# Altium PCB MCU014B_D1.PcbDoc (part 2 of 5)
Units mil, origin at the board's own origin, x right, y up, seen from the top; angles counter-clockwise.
Board outline 2300.04 x 4058 mil, 4 copper layers (TOP, GND, PWR, BOTTOM), stack 48.84 mil thick; 371 components, 238 nets, 1148 pads, 688 vias.
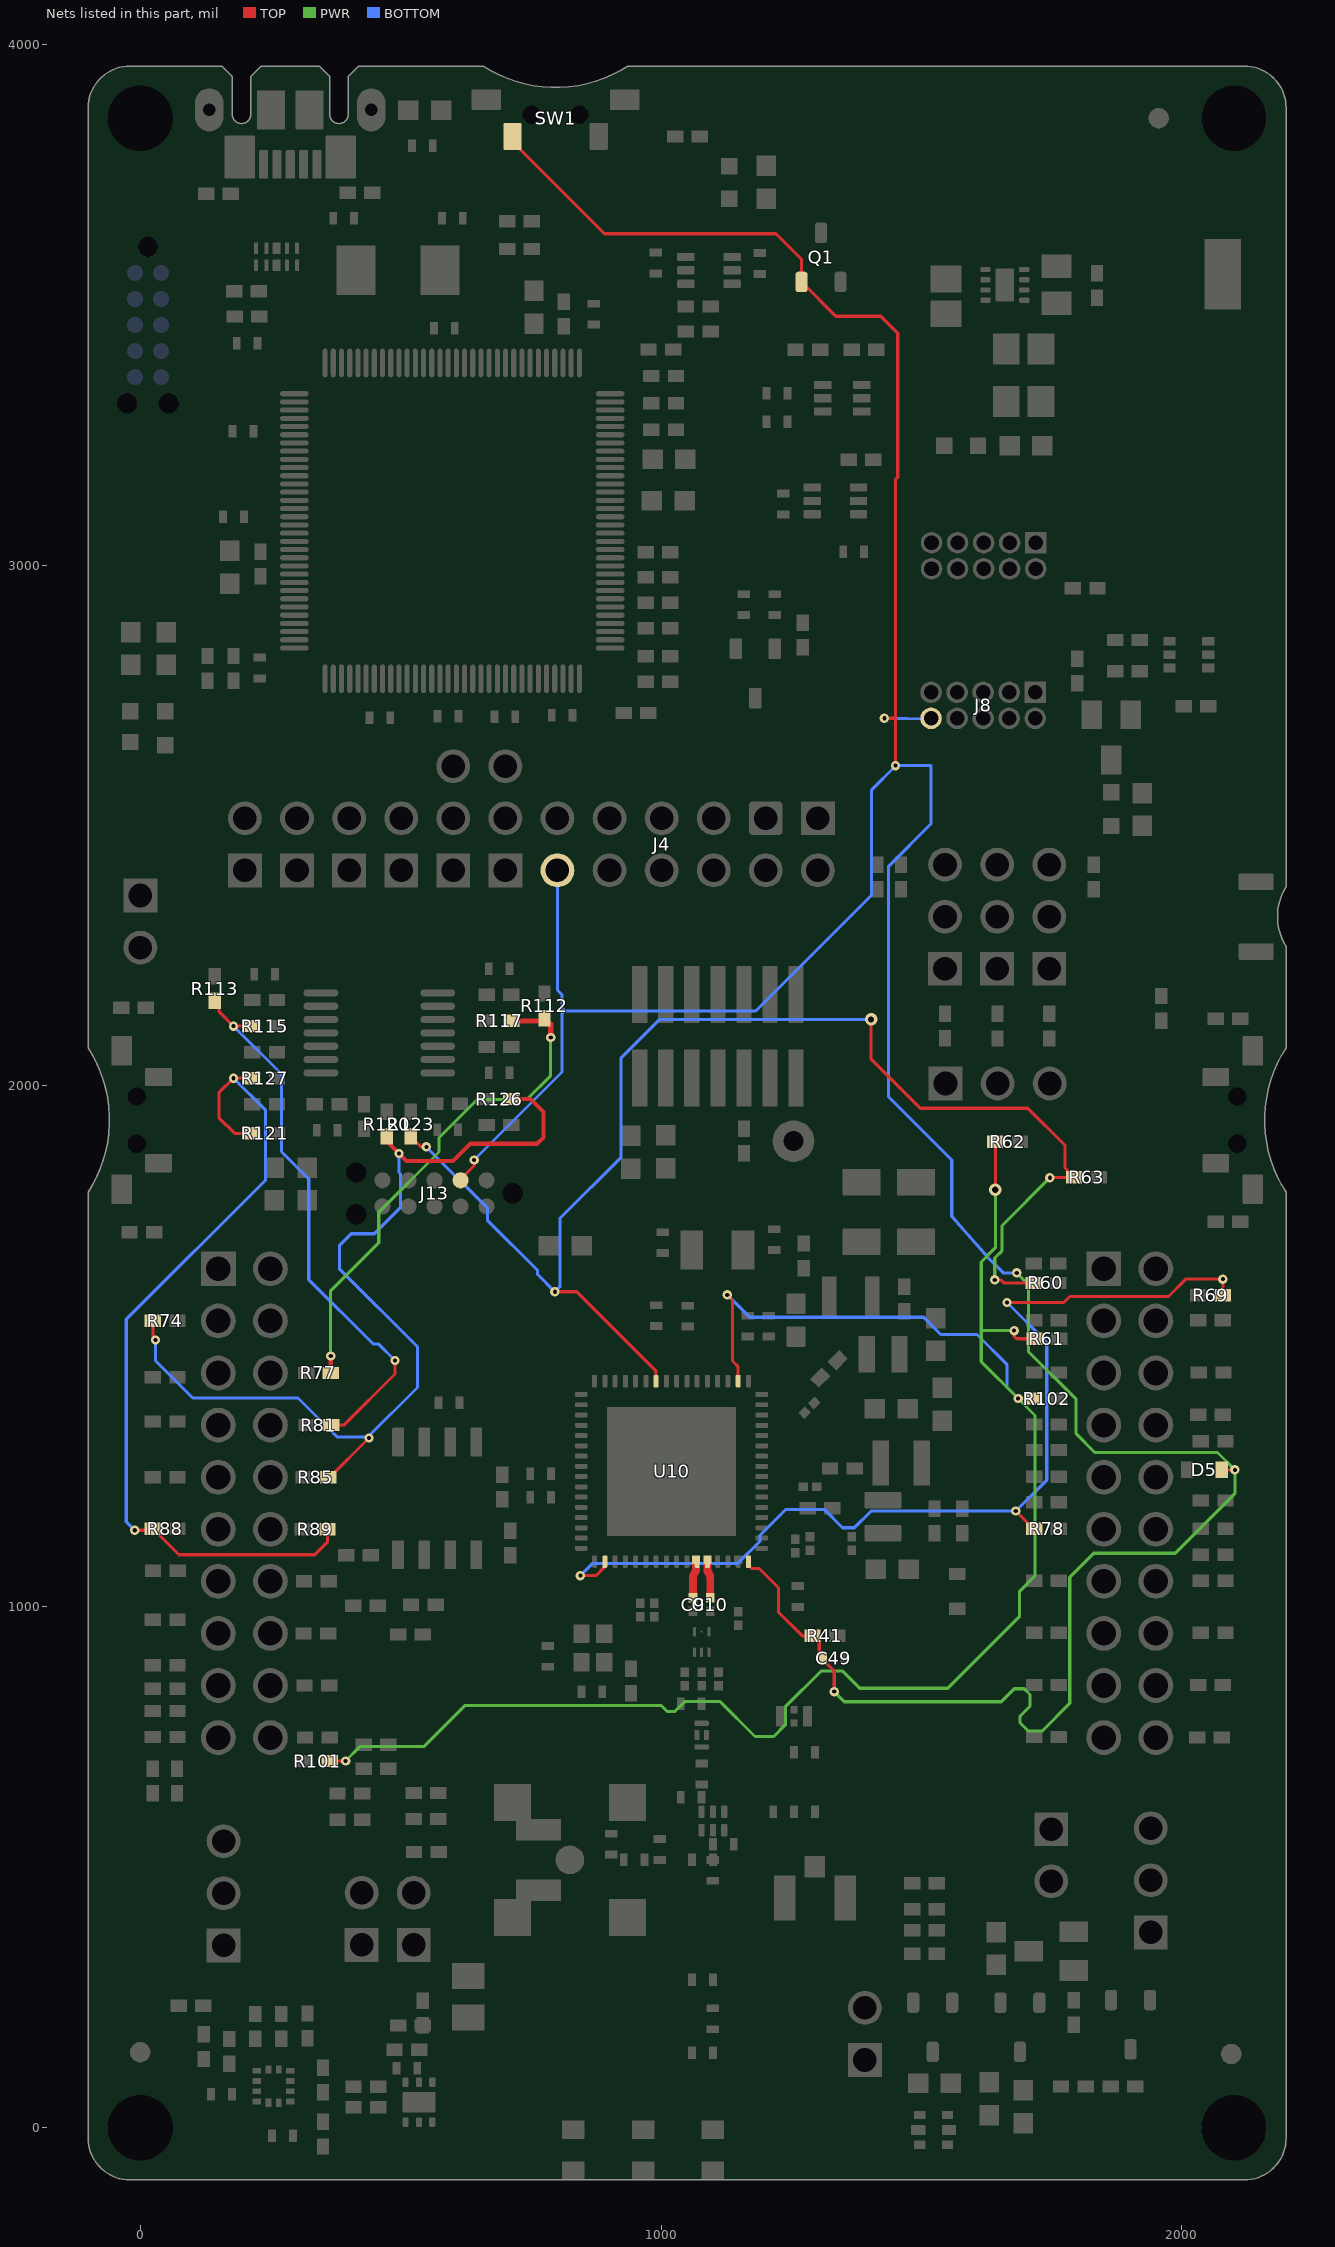
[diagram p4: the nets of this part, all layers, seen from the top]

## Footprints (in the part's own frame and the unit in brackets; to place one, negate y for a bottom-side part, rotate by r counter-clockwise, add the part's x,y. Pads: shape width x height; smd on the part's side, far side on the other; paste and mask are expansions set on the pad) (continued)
PDT0128A [mm] "Thin QFP, 128-Leads, Body 14x14mm, Pitch 0.4mm"
  oval 1.4x0.25 smd: 1(-7.7,6.2) 2(-7.7,5.8) 3(-7.7,5.4) 4(-7.7,5) 5(-7.7,4.6) 6(-7.7,4.2) 7(-7.7,3.8) 8(-7.7,3.4) 9(-7.7,3) 10(-7.7,2.6) 11(-7.7,2.2) 12(-7.7,1.8) 13(-7.7,1.4) 14(-7.7,1) 15(-7.7,0.6) 16(-7.7,0.2) 17(-7.7,-0.2) 18(-7.7,-0.6) 19(-7.7,-1) 20(-7.7,-1.4) 21(-7.7,-1.8) 22(-7.7,-2.2) 23(-7.7,-2.6) 24(-7.7,-3) 25(-7.7,-3.4) 26(-7.7,-3.8) 27(-7.7,-4.2) 28(-7.7,-4.6) 29(-7.7,-5) 30(-7.7,-5.4) 31(-7.7,-5.8) 32(-7.7,-6.2) 65(7.7,-6.2) 66(7.7,-5.8) 67(7.7,-5.4) 68(7.7,-5) 69(7.7,-4.6) 70(7.7,-4.2) 71(7.7,-3.8) 72(7.7,-3.4) 73(7.7,-3) 74(7.7,-2.6) 75(7.7,-2.2) 76(7.7,-1.8) 77(7.7,-1.4) 78(7.7,-1) 79(7.7,-0.6) 80(7.7,-0.2) 81(7.7,0.2) 82(7.7,0.6) 83(7.7,1) 84(7.7,1.4) 85(7.7,1.8) 86(7.7,2.2) 87(7.7,2.6) 88(7.7,3) 89(7.7,3.4) 90(7.7,3.8) 91(7.7,4.2) 92(7.7,4.6) 93(7.7,5) 94(7.7,5.4) 95(7.7,5.8) 96(7.7,6.2)
  oval 0.25x1.4 smd: 33(-6.2,-7.7) 34(-5.8,-7.7) 35(-5.4,-7.7) 36(-5,-7.7) 37(-4.6,-7.7) 38(-4.2,-7.7) 39(-3.8,-7.7) 40(-3.4,-7.7) 41(-3,-7.7) 42(-2.6,-7.7) 43(-2.2,-7.7) 44(-1.8,-7.7) 45(-1.4,-7.7) 46(-1,-7.7) 47(-0.6,-7.7) 48(-0.2,-7.7) 49(0.2,-7.7) 50(0.6,-7.7) 51(1,-7.7) 52(1.4,-7.7) 53(1.8,-7.7) 54(2.2,-7.7) 55(2.6,-7.7) 56(3,-7.7) 57(3.4,-7.7) 58(3.8,-7.7) 59(4.2,-7.7) 60(4.6,-7.7) 61(5,-7.7) 62(5.4,-7.7) 63(5.8,-7.7) 64(6.2,-7.7) 97(6.2,7.7) 98(5.8,7.7) 99(5.4,7.7) 100(5,7.7) 101(4.6,7.7) 102(4.2,7.7) 103(3.8,7.7) 104(3.4,7.7) 105(3,7.7) 106(2.6,7.7) 107(2.2,7.7) 108(1.8,7.7) 109(1.4,7.7) 110(1,7.7) 111(0.6,7.7) 112(0.2,7.7) 113(-0.2,7.7) 114(-0.6,7.7) 115(-1,7.7) 116(-1.4,7.7) 117(-1.8,7.7) 118(-2.2,7.7) 119(-2.6,7.7) 120(-3,7.7) 121(-3.4,7.7) 122(-3.8,7.7) 123(-4.2,7.7) 124(-4.6,7.7) 125(-5,7.7) 126(-5.4,7.7) 127(-5.8,7.7) 128(-6.2,7.7)
  silkscreen extent -7.7,-6.3 6.3,6.99, body extent -8,-8 8,8, height 1.07
PW0014A_N [mm] "TSOP, 14-Leads, Body 5x4.4mm, Pitch 0.65mm, IPC Medium Density"
  oval 1.7x0.35 smd: 1(-2.85,1.95) 2(-2.85,1.3) 3(-2.85,0.65) 4(-2.85,0) 5(-2.85,-0.65) 6(-2.85,-1.3) 7(-2.85,-1.95) 8(2.85,-1.95) 9(2.85,-1.3) 10(2.85,-0.65) 11(2.85,0) 12(2.85,0.65) 13(2.85,1.3) 14(2.85,1.95)
  silkscreen extent -1.85,-2.55 1.85,2.55, body extent -3.21,-2.5 3.21,2.5, height 1
RGK0064B [mm] "VQFN-64"
  rrect42% 0.6x0.24 smd: 1(-4.4,3.75) 2(-4.4,3.25) 3(-4.4,2.75) 4(-4.4,2.25) 5(-4.4,1.75) 6(-4.4,1.25) 7(-4.4,0.75) 8(-4.4,0.25) 9(-4.4,-0.25) 10(-4.4,-0.75) 11(-4.4,-1.25) 12(-4.4,-1.75) 13(-4.4,-2.25) 14(-4.4,-2.75) 15(-4.4,-3.25) 16(-4.4,-3.75) 33(4.4,-3.75) 34(4.4,-3.25) 35(4.4,-2.75) 36(4.4,-2.25) 37(4.4,-1.75) 38(4.4,-1.25) 39(4.4,-0.75) 40(4.4,-0.25) 41(4.4,0.25) 42(4.4,0.75) 43(4.4,1.25) 44(4.4,1.75) 45(4.4,2.25) 46(4.4,2.75) 47(4.4,3.25) 48(4.4,3.75)
  rrect42% 0.24x0.6 smd: 17(-3.75,-4.4) 18(-3.25,-4.4) 19(-2.75,-4.4) 20(-2.25,-4.4) 21(-1.75,-4.4) 22(-1.25,-4.4) 23(-0.75,-4.4) 24(-0.25,-4.4) 25(0.25,-4.4) 26(0.75,-4.4) 27(1.25,-4.4) 28(1.75,-4.4) 29(2.25,-4.4) 30(2.75,-4.4) 31(3.25,-4.4) 32(3.75,-4.4) 49(3.75,4.4) 50(3.25,4.4) 51(2.75,4.4) 52(2.25,4.4) 53(1.75,4.4) 54(1.25,4.4) 55(0.75,4.4) 56(0.25,4.4) 57(-0.25,4.4) 58(-0.75,4.4) 59(-1.25,4.4) 60(-1.75,4.4) 61(-2.25,4.4) 62(-2.75,4.4) 63(-3.25,4.4) 64(-3.75,4.4)
  rrect10% 1x1 on Top Paste: 65(-2.4,-2.4) 65(-2.4,-1.2) 65(-2.4,0) 65(-2.4,1.2) 65(-2.4,2.4) 65(-1.2,-2.4) 65(-1.2,-1.2) 65(-1.2,0) 65(-1.2,1.2) 65(-1.2,2.4) 65(0,-2.4) 65(0,-1.2) 65(0,0) 65(0,1.2) 65(0,2.4) 65(1.2,-2.4) 65(1.2,-1.2) 65(1.2,0) 65(1.2,1.2) 65(1.2,2.4) 65(2.4,-2.4) 65(2.4,-1.2) 65(2.4,0) 65(2.4,1.2) 65(2.4,2.4)
  rrect2% 6.3x6.3 smd paste-4: 65(0,0)
  silkscreen extent -4.7,-4.7 4.7,4.7, body extent -4.5,-4.5 4.5,4.5, height 1
Richwave_RTC6608OSP [mm] "SMD, 6-Leads, Body 1x1mm"
  rrect67% 0.45x0.15 smd: 1(-0.5,0.35) 3(-0.5,-0.35) 4(0.5,-0.35) 5(0.5,0) 6(0.5,0.35)
  rrect100% 0.1x0.1 smd: 2(-0.5,0)
  TOP region: -0.725,-0.076 -0.725,-0.076 -0.726,-0.076 -0.726,-0.075 -0.726,-0.075 -0.726,-0.075 -0.726,0.075 -0.726,0.075 -0.726,0.076 -0.725,0.076 -0.725,0.076 -0.725,0.076 -0.275,0.076 -0.101,0.225 -0.101,0.5 -0.101,0.5 -0.101,0.501 -0.1,0.501 -0.1,0.501 -0.1,0.501 0.1,0.501 0.1,0.501 0.101,0.501 0.101,0.5 0.101,0.5 0.101,0.5 0.101,0.226 0.15,0.226 0.15,0.226 0.151,0.226 0.151,0.225 0.151,0.225 0.151,0.225 0.151,-0.225 0.151,-0.225 0.151,-0.226 0.15,-0.226 0.15,-0.226 0.15,-0.226 0.101,-0.226 0.101,-0.5 0.101,-0.5 0.101,-0.501 0.1,-0.501 0.1,-0.501 0.1,-0.501 -0.1,-0.501 -0.1,-0.501 -0.101,-0.501 -0.101,-0.5 -0.101,-0.5 -0.101,-0.5 -0.101,-0.225 -0.275,-0.076
  silkscreen extent -1.05,0.45 -0.95,0.55, body extent -0.55,-0.55 0.55,0.55, height 0.41
Samtec_FTSH-105-01-x-D-K [mm] "Header, 1.27 mm, 5x2, TH"
  rect 1.05x1.05 hole 0.71: 1(-0.635,2.54)
  round 1.05 hole 0.71: 2(0.635,2.54) 3(-0.635,1.27) 4(0.635,1.27) 5(-0.635,0) 6(0.635,0) 7(-0.635,-1.27) 8(0.635,-1.27) 9(-0.635,-2.54) 10(0.635,-2.54)
  silkscreen extent -2.54,-3.17 2.54,3.2, body extent -2.54,-3.17 2.54,3.1, height 5.73
Samtec_FTSH-107-01-x-DV [mm] "Header, 1.27mm, 7x2, SMT"
  rect 2.79x0.74 smd: 1(-2.035,3.81) 2(2.035,3.81) 3(-2.035,2.54) 4(2.035,2.54) 5(-2.035,1.27) 6(2.035,1.27) 7(-2.035,0) 8(2.035,0) 9(-2.035,-1.27) 10(2.035,-1.27) 11(-2.035,-2.54) 12(2.035,-2.54) 13(-2.035,-3.81) 14(2.035,-3.81)
  silkscreen extent -2.32,4.68 -2.08,4.93, body extent -2.94,-4.48 2.9,4.41, height 5.97
SML-31_Red [mm] "Rohm"
  rect 0.8x0.8 smd: 1(-0.825,0) 2(0.825,0)
  silkscreen extent -1.93,-0.76 1.1,0.76, body extent -0.85,-0.45 0.85,0.45, height 0.91
SOD-523F [mm] "COMCHIP"
  rect 0.6x0.8 smd paste-0.05: 1(-0.85,0) 2(0.85,0)
  body extent -0.9,-0.5 0.9,0.5, height 0.85
SOP-8_150MIL [mm] "SOP, 8-Leads, Body 5.03x4mm, Pitch 1.27mm"
  rrect18% 1.4x0.57 smd: 1(-2.75,1.905) 2(-2.75,0.635) 3(-2.75,-0.635) 4(-2.75,-1.905) 5(2.75,-1.905) 6(2.75,-0.635) 7(2.75,0.635) 8(2.75,1.905)
  silkscreen extent -2,-2.5 2,2.5, body extent -2,-2.5 2,2.5, height 1.76
SOT-23 [mm] "SOT23, 3-Leads, Body 2.9x1.3mm, Pitch 0.95mm, Lead Span 2.5mm, IPC Medium Density"
  rrect50% 1x0.6 smd: 1(-1.2,0.95) 2(-1.2,-0.95) 3(1.2,0)
  silkscreen extent -1.62,-1.5 0.7,1.5, body extent -1.16,-1.45 1.21,1.45, height 1
SOT-363 [mm]
  rect 0.6x0.42 smd mask+0.051: 1(-0.95,0.65) 2(-0.95,0) 3(-0.95,-0.65) 4(0.95,-0.65) 5(0.95,0) 6(0.95,0.65)
  silkscreen extent -0.38,-1.02 0.38,1.02, body extent -1.1,-1.1 1.1,1.1, height 1.12
SSOT-3 [mm] "SuperSOT-3"
  rect 1x1.4 smd: 1(-0.95,-1.1) 2(0.95,-1.1) 3(0,1.1)
  silkscreen extent -1.53,-0.05 1.5,0.77, body extent -1.52,-0.76 1.52,0.76, height 1.12
SW_1188E [mm] "SMD, 4-Leads, Body 7.8x3.5mm"
  rrect10% 1x1.45 smd: 1(-1.1,3.375) 2(-1.1,-3.375)
  rrect11% 1.3x0.9 smd: 3(0.7,2.1) 4(0.7,-2.1)
  round 0 hole 0.9 unplated paste+0.127 mask+0.127: ""(-0.35,1.15) ""(-0.35,-1.15)
  silkscreen extent -1.97,-2.28 0.95,2.28, body extent -2.55,-3.9 1.05,3.9, height 3.5
SW_B3U-3000P [mm] "SMD, 2-Leads, Body 3x2.5mm"
  rrect12% 1.7x0.8 smd: 1(0,1.7) 2(0,-1.7)
  silkscreen extent 1.25,-1.5 1.25,1.5, body extent -1.95,-2 1.25,2, height 1.2
Tag_TC2050-NL#1 [mil] "Footprint for Tag-Connect TC2050 No-Legs cables"
  round 31 smd paste-15.75: 1(-25,100) 2(-25,50) 3(-25,0) 4(-25,-50) 5(-25,-100) 6(25,-100) 7(25,-50) 8(25,0) 9(25,50) 10(25,100)
  round 39 hole 39 unplated mask+5: MH1(0,150) MH2(-40,-150) MH3(40,-150)
  silkscreen extent -105,-200 75,200
Tag_TC2050-NL#2 [mil] "Footprint for Tag-Connect TC2050 No-Legs cables"
  round 31 smd paste-15.75: 1(-25,100) 2(-25,50) 3(-25,0) 4(-25,-50) 5(-25,-100) 6(25,-100) 7(25,-50) 8(25,0) 9(25,50) 10(25,100)
  round 31 hole 39 unplated paste+10 mask+5: MH1(0,150) MH2(-40,-150) MH3(40,-150)
  silkscreen extent -75,-200 75,200
TDK_DEA165538BT-2236B1-H [mm] "SMD, 3-Leads, Body 1.6x0.8mm"
  rrect40% 0.25x0.7 smd: 1(-0.575,0) 3(0.575,0)
  rrect41% 0.5x0.245 smd: 2(0,0.228) 2(0,-0.228)
  silkscreen extent -1,-0.65 1,0.65, body extent -0.87,-0.45 0.87,0.45, height 0.65
TDK_DEA202450BT-1294C1-H [mm] "SMD, 4-Leads, Body 2x1.25mm"
  rect 0.35x0.35 smd: 1(0,0.325) 3(0,-0.325)
  rect 0.45x1 smd: 2(0.65,0) 4(-0.65,0)
  silkscreen extent -1.17,-0.8 1.17,1, body extent -1.07,-0.67 1.07,0.67, height 0.8
TDK_DPX165950DT-8148A1 [mm] "SMD, 6-Leads, Body 1.6x0.8mm"
  rrect33% 0.6x0.3 smd mask+0: 1(-0.45,0.55) 2(-0.45,0) 3(-0.45,-0.55) 4(0.45,-0.55) 5(0.45,0) 6(0.45,0.55)
  silkscreen extent -0.4,-1 0.4,1.2, body extent -0.47,-0.88 0.48,0.87, height 0.7
TESTPOINT [mil]
  round 80 hole 37.99: 1(0,0)
Testpoint_Keystone_Miniature [mil] "Miniature SMT test point"
  rect 135x70 smd: 1(0,0)
  silkscreen extent -78,-46 78,45, body extent -52,-20 52,20, height 61
TI_Stacked_Overlay_Small [mil]
  silkscreen extent -418,-98 418,98
TI_Symbol_Overlay_Small [mil]
  silkscreen extent -90,-88 91,88
TXC_8Y [mm] "SMD, 4-Leads, Body 2x1.6mm"
  rect 0.8x0.9 smd: 1(-0.55,0.7) 2(-0.55,-0.7) 3(0.55,-0.7) 4(0.55,0.7)
  silkscreen extent -0.68,1.35 -0.42,1.6, body extent -0.85,-1.05 0.85,1.05, height 0.56
WEEE_Minimum [mil] "WEEElie bin"
  silkscreen extent -95,-172 99,104
WL-SMCW_YELLOW [mm] "WURTH"
  rect 0.8x0.8 smd: 1(-0.8,0) 2(0.8,0)
  silkscreen extent -1.9,-0.8 1.2,0.8, body extent -0.85,-0.45 0.85,0.45, height 0.8
Wurth_60900213421 [mil] "Shunt, 2.54mm, Black"
  round 1 on Mech3: 0(0,0)
  body extent -98,-48 98,48, height 236
WURTH_61300211121 [mm] "Header, 2.54mm, 2x1, TH"
  rect 1.65x1.65 hole 1.15: 1(-1.27,0)
  round 1.65 hole 1.15: 2(1.27,0)
  silkscreen extent -2.54,-1.27 2.54,1.6, body extent -2.54,-1.27 2.54,1.27, height 8.54
WURTH_61300311121 [mm] "Header, 2.54mm, 3x1, TH"
  rect 1.65x1.65 hole 1.15: 1(-2.54,0)
  round 1.65 hole 1.15: 2(0,0) 3(2.54,0)
  silkscreen extent -4.18,-1.27 3.81,1.27, body extent -3.81,-1.27 3.81,1.27, height 8.54
WURTH_61301021121 [mm] "Header, 2.54mm, 5x2, TH"
  rrect25% 1.65x1.65 hole 1.15: 1(-5.08,-1.27)
  round 1.65 hole 1.15: 2(-5.08,1.27) 3(-2.54,-1.27) 4(-2.54,1.27) 5(0,-1.27) 6(0,1.27) 7(2.54,-1.27) 8(2.54,1.27) 9(5.08,-1.27) 10(5.08,1.27)
  silkscreen extent -6.35,-2.9 6.35,2.54, body extent -6.35,-2.54 6.35,2.54, height 8.54
XTAL_ABM3 [mm] "Abracon recommended land pattern 12.28.10"
  rect 1.9x2.4 smd: 1(-2.05,0) 2(2.05,0)
  silkscreen extent -2.67,-1.78 2.67,1.78, body extent -2.6,-1.7 2.6,1.7, height 1.3
XTAL_ABS07 [mm] "ABRACON"
  rect 1.1x1.9 smd: 1(-1.25,0) 2(1.25,0)
  silkscreen extent -0.4,-1 0.4,1, body extent -1.65,-0.8 1.65,0.8, height 0.9

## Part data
C1: "CAP, CERM, 10 pF, 50 V, +/- 5%, C0G/NP0, 0402", Alternate Manufacturer=----, Alternate PartNumber=GRM1555C1H100JA01D, Cap_Case=0402, Manufacturer=MuRata, Supplier Part Number 1=81-GRM1555C1H100JA1D, TempCo=C0G/NP0, Tolerance_%=5%, Value1=Unknown, Value2=50V, ValueDisplayed=10pF
C2: library part CMP-0085845-1, "CAP, CERM, 8.2 pF, 50 V,+/- 3%, C0G/NP0, 0402", Alternate Manufacturer=MuRata, Alternate PartNumber=GRM1555C1H8R2CA01D, Cap_Case=0402, Manufacturer=Walsin, TempCo=C0G/NP0, Tolerance_%=3%, Value2=50V, ValueDisplayed=8.2pF
C3 C4 C5: library part CMP-0080073-1, "CAP, CERM, 0.5 pF, 50 V,+/- 20%, C0G/NP0, 0402", Cap_Case=0402, Manufacturer=MuRata, Supplier Part Number 1=490-8105-1-ND, TempCo=C0G/NP0, Tolerance_%=20%, Value2=50V, ValueDisplayed=0.5pF
C6: library part CMP-0080075-1, "CAP, CERM, 1.6 pF, 50 V,+/- 7%, C0G/NP0, 0201", Cap_Case=0201, Manufacturer=MuRata, Supplier Part Number 1=490-11312-1-ND, TempCo=C0G/NP0, Tolerance_%=7%, Value2=50V, ValueDisplayed=1.6pF
C7: library part CMP-0085853-1, "CAP, CERM, 1.9 pF, 50 V,+/- 2.6%, C0G/NP0, 0402", Alternate Manufacturer=MuRata, Alternate PartNumber=GRM1555C1H1R9WA01D, Cap_Case=0402, TempCo=C0G/NP0, Tolerance_%=2.6%, Value2=50V, ValueDisplayed=1.9pF
C8: library part CMP-0085854-1, "CAP, CERM, 2.2 pF, 50 V,+/- 4.5%, C0G/NP0, 0402", Alternate Manufacturer=MuRata, Alternate PartNumber=GRM1555C1H2R2BA01D, Cap_Case=0402, TempCo=C0G/NP0, Tolerance_%=4.5%, Value2=50V, ValueDisplayed=2.2pF
C9 C10: library part CMP-0080076-1, "CAP, CERM, 4.7 pF, 50 V,+/- 3%, C0G/NP0, 0201", Cap_Case=0201, Manufacturer=MuRata, Supplier Part Number 1=490-11332-1-ND, TempCo=C0G/NP0, Tolerance_%=3%, Value2=50V, ValueDisplayed=4.7pF
C11: "CAP, CERM, 1 pF, 50 V, +/- 10%, C0G/NP0, 0402", Alternate Manufacturer=----, Cap_Case=0402, Manufacturer=MuRata, PartNumber=GRM1555C1H1R0BA01D, Supplier Part Number 1=490-6206-1-ND, TempCo=C0G/NP0, Tolerance_%=10%, Value1=Unknown, Value2=50V, ValueDisplayed=1pF
C14 C15: library part CMP-0085847-1, "CAP, CERM, 100 pF, 25 V,+/- 5%, C0G/NP0, 0201", Alternate PartNumber=C0603C0G1E101J030BA, Cap_Case=0201, Manufacturer=Yageo, TempCo=C0G/NP0, Tolerance_%=5%, Value2=25V, ValueDisplayed=100pF
C17 C18 C19 C26 C28 C40 C41 C47 C48 C50 C52 C60 C61 C63 C75 C76 C77: library part CMP-0085850-1, "CAP, CERM, 0.1 µF, 16 V,+/- 10%, X7R, 0402", Alternate PartNumber=C1005X5R1A104K050BA, Cap_Case=0402, Manufacturer=Walsin, TempCo=X7R, Tolerance_%=10%, Value2=16V, ValueDisplayed=0.1µF
C20 C22 C24 C29 C30 C31 C35 C71 C72 C73 C74: library part CMP-0085842-1, "CAP, CERM, 0.01 µF, 50 V,+/- 10%, X7R, 0402", Alternate PartNumber=C1005X7R1C103K050BA, Cap_Case=0402, Manufacturer=Walsin, TempCo=X7R, Tolerance_%=10%, Value2=50V, ValueDisplayed=0.01µF
C21 C23: library part CMP-0085851-1, "CAP, CERM, 22 pF, 50 V,+/- 5%, C0G/NP0, 0402", Alternate PartNumber=GRM1555C1H220FA01D, Cap_Case=0402, Manufacturer=Walsin, TempCo=C0G/NP0, Tolerance_%=5%, Value2=50V, ValueDisplayed=22pF
C25 C27 C34 C36 C39: library part CMP-0085848-1, "CAP, CERM, 1 µF, 25 V,+/- 10%, X5R, 0402", Alternate PartNumber=C1005X5R1E105K050BC, Cap_Case=0402, Manufacturer="Samsung Electro-Mechanics", TempCo=X5R, Tolerance_%=10%, Value2=25V, ValueDisplayed=1µF
C32 C33 C38: "CAP, CERM, 0.1 uF, 25 V, +/- 10%, X5R, 0603", Alternate Manufacturer=Walsin, Alternate PartNumber=0603B104K250CT, Cap_Case=0603, Manufacturer=AVX, PartNumber=06033D104KAT2A, Supplier Part Number 1=478-1244-1-ND, TempCo=X5R, Tolerance_%=10%, Value1="0.048 ohm", Value2=25V, ValueDisplayed=0.1uF
C37: "CAP, CERM, 2.2 uF, 16 V, +/- 10%, X5R, 0402", Alternate Manufacturer=SAMSUNG, Alternate PartNumber=CL05A225KA5NUNC, Cap_Case=0402, Manufacturer=TDK, PartNumber=C1005X5R1C225K050BC, Supplier Part Number 1=445-9085-1-ND, TempCo=X5R, Tolerance_%=10%, Value1=Unknown, Value2=16V, ValueDisplayed=2.2uF
C42 C43 C45: "CAP, CERM, 4.7 uF, 6.3 V,+/- 20%, X6S, 0402", Alternate Manufacturer=SAMSUNG, Alternate PartNumber=CL05A475MQ5NRNC, Cap_Case=0402, Manufacturer="Taiyo Yuden", PartNumber=JMK105BC6475MV-F, Supplier Part Number 1=48Y4404, TempCo=X6S, Tolerance_%=20%, Value1=Unknown, Value2=6.3V, ValueDisplayed=4.7uF
C44 C55 C68: library part CMP-0085407-1, "CAP, CERM, 0.6pF, 25 V,+/- 16%, C0G/NP0, 0201", Cap_Case=0201, Manufacturer=MuRata, TempCo=C0G/NP0, Tolerance_%=16%, Value2=25V, ValueDisplayed=0.6pF
C46: library part CMP-0085408-1, "CAP, CERM, 0.5 pF, 25 V,+/- 20%, C0G/NP0, 0201", Cap_Case=0201, Manufacturer=MuRata, TempCo=C0G/NP0, Tolerance_%=20%, Value2=25V, ValueDisplayed=0.5pF
C49: library part CMP-0085842-1, "CAP, CERM, 0.01 µF, 50 V,+/- 10%, X7R, 0402", Alternate PartNumber=GRM155R71E103KA01D, Cap_Case=0402, Manufacturer=Walsin, TempCo=X7R, Tolerance_%=10%, Value2=50V, ValueDisplayed=0.01µF
C51 C59 C62: "CAP, CERM, 10 uF, 10 V,+/- 20%, X6S, 0603", Alternate Manufacturer=SAMSUNG, Alternate PartNumber=CL10A106MP8NNNC, Cap_Case=0603, Manufacturer="Taiyo Yuden", PartNumber=LMK107BC6106MA-T, Supplier Part Number 1=95Y1652, TempCo=X6S, Tolerance_%=20%, Value1=Unknown, Value2=10V, ValueDisplayed=10uF
C53: library part CMP-0085602-1, "CAP, CERM, 0.2pF, 25 V,+/- 50%, C0G/NP0, 0201", Cap_Case=0201, Manufacturer=MuRata, TempCo=C0G/NP0, Tolerance_%=50%, Value2=25V, ValueDisplayed=0.2pF
C54: library part CMP-0009655-3, "CAP, CERM, 0.1 uF, 10 V, +/- 10%, X5R, 0201", Cap_Case=0201, Manufacturer="Samsung Electro-Mechanics", TempCo=X5R, Tolerance_%=10%, Value1=Unknown, Value2=10V, ValueDisplayed=0.1uF
C56 C57: "CAP, CERM, 22 uF, 4 V,+/- 20%, X6S, 0603", Alternate Manufacturer=SAMSUNG, Alternate PartNumber=CL10A226MQ8NRNC, Cap_Case=0603, Manufacturer=MuRata, PartNumber=GRM188C80G226ME15J, Supplier Part Number 1=81-GRM188C80G226ME5J, TempCo=X6S, Tolerance_%=20%, Value1=Unknown, Value2=4V, ValueDisplayed=22uF
C58: library part CMP-0085849-1, "CAP, CERM, 1 µF, 10 V,+/- 20%, X5R, 0402", Alternate PartNumber=GRM155C81A105KA12D, Cap_Case=0402, Manufacturer=Walsin, TempCo=X5R, Tolerance_%=20%, Value2=10V, ValueDisplayed=1µF
C64: "CAP, CERM, 0.1 uF, 10 V, +/- 10%, X5R, 0201", Cap_Case=0201, Manufacturer="Samsung Electro-Mechanics", PartNumber=CL03A104KP3NNNC, TempCo=X5R, Tolerance_%=10%, Value1=Unknown, Value2=10V, ValueDisplayed=0.1uF
C65 C66: library part CMP-0085843-1, "CAP, CERM, 10 pF, 50 V,+/- 5%, C0G/NP0, 0402", Alternate PartNumber=GRM1555C1H100JA01D, Cap_Case=0402, Manufacturer=Walsin, TempCo=C0G/NP0, Tolerance_%=5%, Value2=50V, ValueDisplayed=10pF
C67 C69: library part CMP-0085844-1, "CAP, CERM, 6.2 pF, 50 V,+/- 4%, C0G/NP0, 0402", Alternate PartNumber=GRM1555C1H6R2CA01D, Cap_Case=0402, Manufacturer=Walsin, TempCo=C0G/NP0, Tolerance_%=4%, Value2=50V, ValueDisplayed=6.2pF
C70: library part CMP-0085842-1, "CAP, CERM, 0.01 µF, 50 V,+/- 10%, X7R, 0402", Alternate PartNumber=GRM155R61A103KA01D, Cap_Case=0402, Manufacturer=Walsin, TempCo=X7R, Tolerance_%=10%, Value2=50V, ValueDisplayed=0.01µF
C78 C80: library part CMP-0084772-1, "CAP, CERM, 10 µF, 10 V,+/- 10%, X5R, 0805", Alternate PartNumber=GRM21BR61A106KE19L, Cap_Case=0805, Manufacturer="Samsung Electro-Mechanics", TempCo=X5R, Tolerance_%=10%, Value2=10V, ValueDisplayed=10µF
C79: library part CMP-0085852-1, "CAP, CERM, 22 µF, 16 V,+/- 10%, X5R, 0805", Alternate PartNumber=C2012X5R1C226K125AC, Cap_Case=0805, Manufacturer="Samsung Electro-Mechanics", TempCo=X5R, Tolerance_%=10%, Value2=16V, ValueDisplayed=22µF
C81 C82: "CAP, CERM, 100 uF, 6.3 V, +/- 20%, X5R, 1206", Alternate Manufacturer=SAMSUNG, Alternate PartNumber=CL31A107MQHNNNE, Cap_Case=1206, Manufacturer=MuRata, PartNumber=GRM31CR60J107ME39L, Supplier Part Number 1=490-4539-1-ND, TempCo=X5R, Tolerance_%=20%, Value1="0.003 ohm", Value2=6.3V, ValueDisplayed=100uF
D1 D6 D8: "LED, Red, SMD", Alternate Manufacturer=Rohm, Alternate PartNumber=SML-311UTT86, Color=red, Manufacturer=Everlight, PartNumber=19-217/R6C-AL1M2VY/3T, Supplier Part Number 1=511-1304-1-ND, Value1=W, Value2=1.8V
D2: "LED, Green, SMD", Alternate Manufacturer=Everlight, Alternate PartNumber=19-217/G7C-AN1P2/3T, Color=green, Manufacturer=Lumex, PartNumber=SML-LX0603GW-TR, Supplier Part Number 1=67-1549-1-ND, Value1=W, Value2=2.2V
D3: "LED, Yellow, SMD", Alternate Manufacturer=Everlight, Alternate PartNumber=19-217/G7C-AN1P2/3T, Color=yellow, Manufacturer="Wurth Elektronik", PartNumber=150060YS75000, Supplier Part Number 1=732-4981-1-ND, Value1=W, Value2=2V
D4 D5: library part CMP-0081923-2, "Diode, Schottky, 45 V, 0.03 A, SOD-523F", Alternate PartNumber=CD0603-B00340, Manufacturer="Comchip Technology", Value1=0.03A, Value2=0.37V
D7: "LED, Rgb, SMD", Alternate Manufacturer=Everlight, Alternate PartNumber=19-337-R6GHBHC-C02-2T, Color=RGB, PartNumber=EAST1616RGBA8, Value1=W, Value2=3.7V
E1: "WLAN ANTENNA 802.11, SMD", Alternate Manufacturer=----, Manufacturer=Ethertronics, PartNumber=M830520
FID1 FID2 FID3 FID4 FID5 FID6: "Fiducial mark.  There is nothing to buy or mount.", Manufacturer=N/A
FL1: "Multilayer Chip Band Pass Filter For 2.4GHz W-LAN/Bluetooth, SMD", Alternate Manufacturer=----, Manufacturer=TDK, PartNumber=DEA202450BT-1294C1-H, Supplier Part Number 1=445-172335-1-ND
FL2: "Multilayer Band Pass Filter For 5GHz W-LAN/LTE-U", Alternate Manufacturer=----, Manufacturer=TDK, PartNumber=DEA165538BT-2236B1-H
J1: "Connector, SMA, Vertical, Gold, SMT", Alternate Manufacturer=??, Alternate PartNumber=SMA-050710, Manufacturer="Hus-Tsan Group Co., Ltd.", PartNumber=SMA-10V21-TGG
J2 J3: library part CMP-0075320-1, "Receptacle, Ultra Miniature Coaxial, Male Pin, 50 ohm, SMT", Alternate Manufacturer=----, Color=Beige, Manufacturer="Hirose Electric Co. Ltd.", Supplier Part Number 1=H122041-ND
J4: "Header, 2.54 mm, 5x2, Gold, TH", Alternate Manufacturer=----, Current_A=3A, Manufacturer="Wurth Elektronik", PartNumber=61301021121, Supplier Part Number 1=732-2672-ND, Voltage_V=250V
J5: "Footprint for Tag-Connect TC2050 No-Legs cables", Manufacturer=Tag-Connect, PartNumber=TC2050-IDC-NL-FP
J6: "Receptacle, USB 2.0, Micro B, 5 Position, R/A, SMT", Alternate Manufacturer=----, Color=Black, Current_A=1.8A, Manufacturer=Molex, PartNumber=1051640001, Supplier Part Number 1=WM11263CT-ND, Voltage_V=30V
J7 J8: "Header, 1.27 mm, 5x2, Gold, TH", Alternate Manufacturer=----, Color=Black, Manufacturer=Samtec, PartNumber=FTSH-105-01-F-D-K, Supplier Part Number 1=FTSH-105-01-F-D-K-ND
J9 J10 J14 J15 J16 J17 J26 J27: "Header, 2.54 mm, 3x1, Gold, TH", Alternate Manufacturer=----, Manufacturer="Wurth Elektronik", PartNumber=61300311121, Supplier Part Number 1=732-5316-ND
J11: "Header, 1.27mm, 7x2, Gold, SMT", Alternate Manufacturer=----, Color=Black, Current_A=3.3A, Manufacturer=Samtec, PartNumber=FTSH-107-01-F-DV, Supplier Part Number 1=FTSH-107-01-F-DV-ND
J12 J18 J19 J20 J21 J22 J23 J24 J25 J28: "Header, 2.54 mm, 2x1, Gold, TH", Alternate Manufacturer=----, Manufacturer="Wurth Elektronik", PartNumber=61300211121, Supplier Part Number 1=732-5315-ND
J13: library part CMP-0075101-1, "Footprint for Tag-Connect TC2050 No-Legs cables", Manufacturer=Tag-Connect
L1: library part CMP-0080371-1, "Inductor, Multilayer, Air Core, 22 nH, 0.35 A, 0.42 ohm, AEC-Q200 Grade 1, SMD", Manufacturer=MuRata, Supplier Part Number 1=490-15154-1-ND, Value1="0.42 ohm", Value2=0.35A, ValueDisplayed=22nH
L2: library part CMP-0080372-1, "Inductor, Multilayer, Air Core, 6.8 nH, 0.6 A, 0.22 ohm, AEC-Q200 Grade 1, SMD", Manufacturer=MuRata, Supplier Part Number 1=490-15174-1-ND, Value1="0.22 ohm", Value2=0.6A, ValueDisplayed=6.8nH
L3: "Inductor, Multilayer, Air Core, 3.9 nH, 0.75 A, 0.14 ohm, SMD", Manufacturer=MuRata, PartNumber=LQG15HS3N9S02D, Supplier Part Number 1=490-2617-1-ND, Value1="0.14 ohm", Value2=0.75A, ValueDisplayed=3.9nH
L4: library part CMP-0080374-1, "Inductor, Multilayer, Air Core, 2.7 nH, 0.9 A, 0.07 ohm, AEC-Q200 Grade 1, SMD", Manufacturer=MuRata, Supplier Part Number 1=490-15215-1-ND, Value1="0.07 ohm", Value2=0.9A, ValueDisplayed=2.7nH
L5 L6: "Ferrite Bead, 10 ohm @ 100 MHz, 1 A, 0402", Alternate Manufacturer=----, Manufacturer=MuRata, PartNumber=BLM15AG100SN1D, Supplier Part Number 1=490-5176-1-ND, Value1="0.025 ohm", Value2=1A, ValueDisplayed="10 ohm"
L7 L10: "Inductor, Multilayer, Ferrite, 2.2 uH, 1.2 A, 0.11 ohm, SMD", Alternate Manufacturer=----, Manufacturer=MuRata, PartNumber=LQM2MPN2R2NG0, Supplier Part Number 1=490-7786-1-ND, Value1="0.11 ohm", Value2=1.2A, ValueDisplayed=2.2uH
L9: "Inductor, Multilayer, Ferrite, 1 uH, 1.6 A, 0.055 ohm, SMD", Alternate Manufacturer=----, Manufacturer=MuRata, PartNumber=LQM2HPN1R0MG0L, Supplier Part Number 1=490-5112-1-ND, Value1="0.055 ohm", Value2=1.6A, ValueDisplayed=1uH
L11: "Inductor, Multilayer, Ferrite, 10 uH, 0.7 A, 0.364 ohm, SMD", Alternate Manufacturer=----, Manufacturer=TDK, PartNumber=MLP2520S100MT0S1, Supplier Part Number 1=445-9504-1-ND, Value1="0.364 ohm", Value2=0.7A, ValueDisplayed=10uH
L12: "Inductor, Wirewound, 2.2 uH, 1 A, 0.143 ohm, SMD", Alternate Manufacturer=----, Manufacturer="Taiyo Yuden", PartNumber=BRC2012T2R2MD, Supplier Part Number 1=587-2905-1-ND, Value1="0.143 ohm", Value2=1A, ValueDisplayed=2.2uH
Label1: "Thermal Transfer Printable Labels, 0.650\" W x 0.200\" H - 10,000 per roll", Alternate Manufacturer=----, Manufacturer=Brady, PartNumber=THT-14-423-10, Supplier Part Number 1=97C5133
Logo1: library part CMP-0074769-1
Logo2 Logo6: library part CMP-0074838-1, "Texas Instrument Corporate Signature"
Logo3: library part CMP-0074847-1, "FCC_disclaimer"
Logo4: library part CMP-0074840-1, "ESD Susceptible Symbol"
Logo5: "CE Mark"
P1 P2: library part CMP-0075108-1, "Receptacle, 2.54 mm, 10x2, Gold, TH", Alternate PartNumber="Order Directly from Major League", Manufacturer="Major League Electronics"
Q1 Q4 Q5 Q7: "MOSFET, N-CH, 50 V, 0.22 A, SOT-23", Alternate Manufacturer=ON, Alternate PartNumber=BSS138LT1G, Manufacturer="Fairchild Semiconductor", PartNumber=BSS138, Supplier Part Number 1=BSS138CT-ND, Value2="1.7 nC"
Q2: "MOSFET, 2-CH, P-CH, -50 V, -0.13 A, AEC-Q101, SOT-363", Alternate Manufacturer=----, Manufacturer="Diodes Inc.", PartNumber=BSS84DW-7-F, Supplier Part Number 1=BSS84DW-FDICT-ND
Q3 Q6: "MOSFET, P-CH, -30 V, -1.5 A, SSOT-3", Alternate Manufacturer=----, Manufacturer="Fairchild Semiconductor", PartNumber=FDN358P, Supplier Part Number 1=FDN358PCT-ND, Value1=0, Value2="4 nC"
R1: library part CMP-0027008-4, "RES, 0, 5%, 0.05 W, 0201", Manufacturer=Vishay-Dale, Power_W=50mW, Supplier Part Number 1=72M6743, TempCo=ppm/C, Tolerance_%=5%, Value2=0.05W, Value_Code=0000, ValueDisplayed=0
R2 R3 R4 R6 R42 R43 R47 R48 R49 R50 R54 R60 R61 R65 R67 R68 R69 R70 R71 R72 R73 R74 R75 R76 R77 R78 R79 R80 R81 R82 R83 R84 R85 R86 R87 R88 R89 R90 R91 R92 R93 R94 R95 R96 R97 R98 R99 R100 R101 R102 R103 R104 R105 R106 R107 R108 R109 R110 R111 R112 R113 R120 R121 R123 R125 R130 R131 R132 R135 R136 R137 R138 R139 R140 R142 R143 R144 R145 R146 R147 R148 R149 R165 R167 R168 R172: "RES, 0, 5%, 0.063 W, 0402", Alternate Manufacturer=YAGEO, Alternate PartNumber=RC0402JR-070RL, Manufacturer=Panasonic, PartNumber=ERJ-2GE0R00X, Power_W=63mW, Supplier Part Number 1=P0.0JCT-ND, TempCo="600 ppm/C", Tolerance_%=5%, Value2=0.063W, Value_Code=0000, ValueDisplayed=0
R5 R7 R9 R10 R11 R12 R13 R34 R36: "RES, 33.0, 1%, 0.1 W, 0402", Alternate Manufacturer=YAGEO, Alternate PartNumber=RC0402FR-0733RL, Manufacturer=Panasonic, PartNumber=ERJ-2RKF33R0X, Power_W=100mW, Supplier Part Number 1=P33.0LCT-ND, TempCo="100 ppm/C", Tolerance_%=1%, Value2=0.1W, Value_Code=33R0, ValueDisplayed=33.0
R8: "RES, 100, 5%, 0.063 W, AEC-Q200 Grade 0, 0402", Alternate Manufacturer=YAGEO, Alternate PartNumber=RC0402JR-07100RL, Manufacturer=Vishay-Dale, PartNumber=CRCW0402100RJNED, Power_W=63mW, Supplier Part Number 1=541-100JCT-ND, TempCo="200 ppm/C", Tolerance_%=5%, Value2=0.063W, Value_Code=100R, ValueDisplayed=100
R14 R33 R41 R44 R45 R46 R56 R62 R63 R152 R161 R169 R170 R171: "RES, 100 k, 5%, 0.063 W, AEC-Q200 Grade 0, 0402", Alternate Manufacturer=YAGEO, Alternate PartNumber=RC0402JR-07100KL, Manufacturer=Vishay-Dale, PartNumber=CRCW0402100KJNED, Power_W=63mW, Supplier Part Number 1=541-100KJCT-ND, TempCo="200 ppm/C", Tolerance_%=5%, Value2=0.063W, Value_Code=100k
R15: "RES, 330 k, 5%, 0.063 W, AEC-Q200 Grade 0, 0402", Alternate Manufacturer=YAGEO, Alternate PartNumber=RC0402JR-07330KL, Manufacturer=Vishay-Dale, PartNumber=CRCW0402330KJNED, Power_W=63mW, Supplier Part Number 1=541-330KJCT-ND, TempCo="200 ppm/C", Tolerance_%=5%, Value2=0.063W, Value_Code=330k
R16: "RES, 220 k, 5%, 0.063 W, AEC-Q200 Grade 0, 0402", Alternate Manufacturer=YAGEO, Alternate PartNumber=RC0402JR-07220KL, Manufacturer=Vishay-Dale, PartNumber=CRCW0402220KJNED, Power_W=63mW, Supplier Part Number 1=541-220KJCT-ND, TempCo="200 ppm/C", Tolerance_%=5%, Value2=0.063W, Value_Code=220k
R17 R26 R59 R154 R155 R156 R157: "RES, 10 k, 5%, 0.063 W, AEC-Q200 Grade 0, 0402", Alternate Manufacturer=YAGEO, Alternate PartNumber=RC0402JR-0710KL, Manufacturer=Vishay-Dale, PartNumber=CRCW040210K0JNED, Power_W=63mW, Supplier Part Number 1=541-10KJCT-ND, TempCo="200 ppm/C", Tolerance_%=5%, Value2=0.063W, Value_Code=10k0, ValueDisplayed=10k
R18 R19: "RES, 220, 5%, 0.1 W, AEC-Q200 Grade 0, 0603", Alternate Manufacturer=YAGEO, Alternate PartNumber=RC0603JR-07220RL, Manufacturer=Vishay-Dale, PartNumber=CRCW0603220RJNEA, Power_W=100mW, Supplier Part Number 1=541-220GCT-ND, TempCo="200 ppm/C", Tolerance_%=5%, Value2=0.1W, Value_Code=220R, ValueDisplayed=220
R20 R158 R160: "RES, 270, 5%, 0.1 W, AEC-Q200 Grade 0, 0603", Alternate Manufacturer=YAGEO, Alternate PartNumber=RC0603JR-07270RL, Manufacturer=Vishay-Dale, PartNumber=CRCW0603270RJNEA, Power_W=100mW, Supplier Part Number 1=541-270GCT-ND, TempCo="200 ppm/C", Tolerance_%=5%, Value2=0.1W, Value_Code=270R, ValueDisplayed=270
R21: "RES, 100, 1%, 0.1 W, 0402", Alternate Manufacturer=YAGEO, Alternate PartNumber=RC0402FR-07100RL, Manufacturer=Panasonic, PartNumber=ERJ-2RKF1000X, Power_W=100mW, Supplier Part Number 1=P100LCT-ND, TempCo="100 ppm/C", Tolerance_%=1%, Value2=0.1W, Value_Code=100R, ValueDisplayed=100
R22 R23 R24 R25 R28 R31 R35 R37 R150 R151 R159: "RES, 1.0 k, 5%, 0.063 W, AEC-Q200 Grade 0, 0402", Alternate Manufacturer=YAGEO, Alternate PartNumber=RC0402JR-071KL, Manufacturer=Vishay-Dale, PartNumber=CRCW04021K00JNED, Power_W=63mW, Supplier Part Number 1=541-1.0KJCT-ND, TempCo="200 ppm/C", Tolerance_%=5%, Value2=0.063W, Value_Code=1k00, ValueDisplayed=1.0k
R27: "RES, 100 k, 5%, 0.1 W, AEC-Q200 Grade 0, 0603", Alternate Manufacturer=YAGEO, Alternate PartNumber=RC0603JR-07100KL, Manufacturer=Vishay-Dale, PartNumber=CRCW0603100KJNEA, Power_W=100mW, Supplier Part Number 1=541-100KGCT-ND, TempCo="200 ppm/C", Tolerance_%=5%, Value2=0.1W, Value_Code=100k
R29: "RES, 100, 1%, 0.063 W, AEC-Q200 Grade 0, 0402", Alternate Manufacturer=YAGEO, Alternate PartNumber=RC0402FR-07100RL, Manufacturer=Vishay-Dale, PartNumber=CRCW0402100RFKED, Power_W=63mW, Supplier Part Number 1=541-100LCT-ND, TempCo="100 ppm/C", Tolerance_%=1%, Value2=0.063W, Value_Code=100R, ValueDisplayed=100
R30: "RES, 4.87 k, 1%, 0.1 W, AEC-Q200 Grade 0, 0603", Alternate Manufacturer=YAGEO, Alternate PartNumber=RC0603FR-074K87L, Manufacturer=Vishay-Dale, PartNumber=CRCW06034K87FKEA, Power_W=100mW, Supplier Part Number 1=541-4.87KHCT-ND, TempCo="100 ppm/C", Tolerance_%=1%, Value2=0.1W, Value_Code=4k87, ValueDisplayed=4.87k
R32: "RES, 51, 5%, 0.063 W, AEC-Q200 Grade 0, 0402", Alternate Manufacturer=YAGEO, Alternate PartNumber=RC0402JR-0751RL, Manufacturer=Vishay-Dale, PartNumber=CRCW040251R0JNED, Power_W=63mW, Supplier Part Number 1=541-51JCT-ND, TempCo="200 ppm/C", Tolerance_%=5%, Value2=0.063W, Value_Code=51R0, ValueDisplayed=51
R38 R39: "RES, 33, 5%, 0.1 W, AEC-Q200 Grade 0, 0603", Alternate Manufacturer=YAGEO, Alternate PartNumber=RC0603JR-0733RL, Manufacturer=Vishay-Dale, PartNumber=CRCW060333R0JNEA, Power_W=100mW, Supplier Part Number 1=541-33GCT-ND, TempCo="200 ppm/C", Tolerance_%=5%, Value2=0.1W, Value_Code=33R0, ValueDisplayed=33
R40 R64 R66 R166: "RES, 0, 5%, 0.1 W, 0603", Alternate Manufacturer=YAGEO, Alternate PartNumber=RC0603FR-070RL, Manufacturer=Panasonic, PartNumber=ERJ-3GEY0R00V, Power_W=100mW, Supplier Part Number 1=P0.0GCT-ND, TempCo="600 ppm/C", Tolerance_%=5%, Value2=0.1W, Value_Code=0000, ValueDisplayed=0
R51: "RES, 270, 5%, 0.063 W, AEC-Q200 Grade 0, 0402", Alternate Manufacturer=YAGEO, Alternate PartNumber=RC0402JR-07270RL, Manufacturer=Vishay-Dale, PartNumber=CRCW0402270RJNED, Power_W=63mW, Supplier Part Number 1=541-270JCT-ND, TempCo="200 ppm/C", Tolerance_%=5%, Value2=0.063W, Value_Code=270R, ValueDisplayed=270
R52 R53 R57 R58: "RES, 69.8 k, 1%, 0.063 W, AEC-Q200 Grade 0, 0402", Alternate Manufacturer=YAGEO, Alternate PartNumber=RC0402FR-0769K8L, Manufacturer=Vishay-Dale, PartNumber=CRCW040269K8FKED, Power_W=63mW, Supplier Part Number 1=541-69.8KLCT-ND, TempCo="100 ppm/C", Tolerance_%=1%, Value2=0.063W, Value_Code=69k8, ValueDisplayed=69.8k
R55: "RES, 2.2 k, 5%, 0.063 W, AEC-Q200 Grade 0, 0402", Alternate Manufacturer=YAGEO, Alternate PartNumber=RC0402JR-072K2L, Manufacturer=Vishay-Dale, PartNumber=CRCW04022K20JNED, Power_W=63mW, Supplier Part Number 1=541-2.2KJCT-ND, TempCo="200 ppm/C", Tolerance_%=5%, Value2=0.063W, Value_Code=2k20, ValueDisplayed=2.2k
R114 R116 R122 R124: "RES, 470, 1%, 0.1 W, AEC-Q200 Grade 0, 0402", Alternate Manufacturer=YAGEO, Alternate PartNumber=RC0402FR-07470RL, Manufacturer=Panasonic, PartNumber=ERJ-2RKF4700X, Power_W=100mW, Supplier Part Number 1=P470LCT-ND, TempCo="100 ppm/C", Tolerance_%=1%, Value2=0.1W, Value_Code=470R, ValueDisplayed=470
R115 R117 R126 R127: "RES, 576 k, 1%, 0.063 W, AEC-Q200 Grade 0, 0402", Alternate Manufacturer=YAGEO, Alternate PartNumber=RC0402FR-07576KL, Manufacturer=Vishay-Dale, PartNumber=CRCW0402576KFKED, Power_W=63mW, Supplier Part Number 1=541-576KLCT-ND, TempCo="100 ppm/C", Tolerance_%=1%, Value2=0.063W, Value_Code=576k
R118 R119 R128 R129: "RES, 422 k, 1%, 0.063 W, AEC-Q200 Grade 0, 0402", Alternate Manufacturer=YAGEO, Alternate PartNumber=RC0402FR-07422KL, Manufacturer=Vishay-Dale, PartNumber=CRCW0402422KFKED, Power_W=63mW, Supplier Part Number 1=541-422KLCT-ND, TempCo="100 ppm/C", Tolerance_%=1%, Value2=0.063W, Value_Code=422k
R133 R134: "RES, 3.3 k, 5%, 0.063 W, AEC-Q200 Grade 0, 0402", Alternate Manufacturer=YAGEO, Alternate PartNumber=RC0402JR-073K3L, Manufacturer=Vishay-Dale, PartNumber=CRCW04023K30JNED, Power_W=63mW, Supplier Part Number 1=541-3.3KJCT-ND, TempCo="200 ppm/C", Tolerance_%=5%, Value2=0.063W, Value_Code=3k30, ValueDisplayed=3.3k
R141: "RES, 0, 5%, 0.125 W, 0805", Alternate Manufacturer=----, Manufacturer=Panasonic, PartNumber=ERJ-6GEY0R00V, Power_W=125mW, Supplier Part Number 1=P0.0ACT-ND, TempCo="600 ppm/C", Tolerance_%=5%, Value2=0.125W, Value_Code=0000, ValueDisplayed=0
R153: "RES, 100 k, 1%, 0.1 W, 0402", Alternate Manufacturer=YAGEO, Alternate PartNumber=RC0402FR-07100KL, Manufacturer=Panasonic, PartNumber=ERJ-2RKF1003X, Power_W=100mW, TempCo="100 ppm/C", Tolerance_%=1%, Value2=0.1W, Value_Code=100k
R162 R163 R164: "RES, 750, 5%, 0.1 W, 0603", Alternate Manufacturer=----, Manufacturer="Yageo America", PartNumber=RC0603JR-07750RL, Power_W=100mW, Supplier Part Number 1=311-750GRCT-ND, TempCo="100 ppm/C", Tolerance_%=5%, Value2=0.1W, Value_Code=750R, ValueDisplayed=750
SH-J3 SH-J4 SH-J5 SH-J6 SH-J7 SH-J8 SH-J9 SH-J10 SH-J11 SH-J12 SH-J13 SH-J14 SH-J15 SH-J16 SH-J17 SH-J18 SH-J19 SH-J20 SH-J21 SH-J22 SH-J23: "Shunt, 2.54mm, Gold, Black", Alternate Manufacturer=----, Manufacturer="Wurth Elektronik", PartNumber=60900213421, Supplier Part Number 1=732-2678-ND
SW1 SW2 SW3: "Switch, SPST, 0.05 A, 12 VDC, SMD", Alternate Manufacturer=----, CurrentRating_mA=50A, Manufacturer=Diptronics, PartNumber=1188E-1K2-V-TR
SW4: library part CMP-0076764-1, "Switch, SPST-NO, Off-Mom, 0.05 A, 12 VDC, SMT", CurrentRating_mA=50A, Manufacturer="Omron Electronic Components", Supplier Part Number 1=SW1022CT-ND
TP1: "TEST POINT.  No entry in BOM.", Manufacturer=N/A
TP2: library part CMP-0055152-1, "Test Point, Miniature, SMT", Alternate Manufacturer=----, Manufacturer=Keystone, Supplier Part Number 1=36-5015TR-ND
U1: "Multilayer Diplexer for 2.4GHz W-LAN & Bluetooth / 5GHz W-LAN", Alternate Manufacturer=----, Manufacturer=TDK, PartNumber=DPX165950DT-8148A1, Supplier Part Number 1=445-174759-1-ND
U2: library part CMP-0065464-1, "0.03 GHz-6 GHz SPDT Switch", Alternate Manufacturer=----, Alternate PartNumber="Order Directly from Richwave", Manufacturer=Richwave
U3: "Tiva C Series Microcontroller, 1024 KB Flash, 256 KB SRAM, 12 Bit, 20 Channels, -40 to 85 degC, 128-Pin TQFP (PDT), Green (RoHS & no Sb/Br), Tape and Reel", Alternate Manufacturer=----, Manufacturer="Texas Instruments", PartNumber=TM4C1294NCPDTI3R, Temperature Range="-40 to 85 degC"
U4 U7 U8: "Single-Bit Dual-Supply Bus Transceiver with Configurable Voltage Translation and 3-State Outputs, DCK0006A, LARGE T&R", Alternate Manufacturer="Texas Instruments", Alternate PartNumber=SN74LVC1T45DCKT, F @ Nom Voltage(Max)(Mhz)=150, Generic Part Number=SN74LVC1T45, ICC @ Nom Voltage(Max)(mA)=0.004, Operating Temperature Range(C)="-40 to 85", PartNumber=SN74LVC1T45DCKR, Rating=Catalog, tpd @ Nom Voltage(Max)(ns)=15.5,8,5.8,4.4, Voltage(Nom)(V)=1.8,2.5,3.3,5
U5: "ESD Solution for High-Speed Differential Interface, 4 Channels, -40 to +85 degC,10-pin SON (DQA), Green (RoHS & no Sb/Br)", Alternate Manufacturer=----, Breakdown Voltage(Min)(V)=9, Differential Capacitance(pF)=0.05, IO Capacitance(Typ)(pF)=0.8, IO Leakage Current(nA)=10, Manufacturer="Texas Instruments", PartNumber=TPD4S010DQAR
U6: "Precision Micropower Shunt Voltage Reference, 0.2% accuracy, 2.5 V, 15 ppm / degC, 15 mA, -40 to 85 degC, 3-pin SOT-23 (DBZ), Green (RoHS & no Sb/Br)", Alternate Manufacturer=----, Manufacturer="Texas Instruments", PartNumber=LM4040B25IDBZR, Rating=Catalog, Temp Coeff(Max)(ppm/ degree C)=100, Temp Coeff(Typ)(ppm/ degree C)=15
U9: "ULTRA LOW POWER, 32M-BIT [x 1/x 2/x 4] CMOS MXSMIO(SERIAL MULTI I/O) FLASH MEMORY, SOP-8", Alternate Manufacturer=----, Manufacturer="Macronix International Co., LTD", PartNumber=MX25R3235FM1IL0
U10: library part CMP-0065220-6, "SimpleLink Wi-Fi and Internet-of-Things Solution, a Single-Chip Wireless MCU, RGK0064B (VQFN-64)", Alternate Manufacturer="Texas Instruments"
U11: "Low Cost, Low Power, Rail-to-Rail Operational Amplifier MicroAmplifier(TM) Series, 2.7 to 5.5 V, -55 to 125 degC, 14-pin SOP (PW14), Green (RoHS & no Sb/Br)", Alternate Manufacturer=----, Manufacturer="Texas Instruments", PartNumber=OPA4342EA/250, Rating=Catalog, Total Supply Voltage(Max)(+5V is 5, +/-5V is 10)=5.5, Total Supply Voltage(Min)(+5V is 5, +/-5V is 10)=2.7
U12: library part CMP-0013432-6, "High-Accuracy, Low-Power, Digital Temperature Sensor with SMBus and Two-Wire Serial Interface, DRV0006A (WSON-6)", Alternate Manufacturer="Texas Instruments", Alternate PartNumber=TMP116AIDRVT
U13: library part CMP-0004812-1, "14 Bit, Digital, Triaxial Acceleration Sensor with Intelligent On-Chip Motion-Triggered Interrupt Controller, 12LGA", Manufacturer="Bosch Solar Energy", Supplier Part Number 1=828-1033-1-ND
U14: "Buck Step Down Regulator with 3 to 17 V Input and 3.3 V Output, -40 to 85 degC, 8-Pin WSON (DSG), Green (RoHS & no Sb/Br)", Alternate Manufacturer=----, Manufacturer="Texas Instruments", PartNumber=TPS62162DSGR, Rating=Catalog, Switch Current Limit(Typ)(A)=1.8
Y1: "Crystal, 16 MHz, 18 pF, SMD", Alternate Manufacturer=----, Frequency_Fixed=16MHz, Frequency Stability=+/-30ppm, Manufacturer="Abracon Corporation", PartNumber=ABM3-16.000MHZ-D2Y-T, Supplier Part Number 1=535-10638-1-ND
Y2: "CRYSTAL, 32.768KHz, 9PF, SMD", Alternate Manufacturer=----, Frequency_Fixed=32.768kHz, Frequency Stability=+/-20ppm, Manufacturer="Abracon Corporation", PartNumber=ABS07-32.768KHZ-9-T, Supplier Part Number 1=535-9544-1-ND
Y3: library part CMP-0077111-2, "Crystal, 40 MHz, 8 pF, SMD", Alternate Manufacturer=----, Alternate PartNumber="Order Directly from TXC", Frequency_Fixed=40MHz, Frequency Stability=±15ppm, Manufacturer="TXC Corporation"
ZZ1: library part CMP-0003616-3
ZZ2: library part CMP-0077236-1
ZZ3: library part CMP-0077237-1
ZZ4: library part CMP-0077238-1

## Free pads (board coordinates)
  round 125 hole 125 unplated mask+5: 1(0,0) 1(0,3858) 1(2100,0) 1(2100,3858)
  rrect0% 15x16.73 smd paste-100 mask-100: 2(1066.71,1090.22) 2(1088.9,1090.22)
  rrect0% 16.73x16.73 smd paste-100 mask-100: 2(1148.06,1090.22)

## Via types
v1: diameter 24, hole 12, TOP to BOTTOM, tented both sides, 230 vias
v2: diameter 18, hole 8, TOP to BOTTOM, tented both sides, 218 vias
v3: diameter 20, hole 10, TOP to BOTTOM, tented both sides, 159 vias
v4: diameter 19.68, hole 7.87, TOP to BOTTOM, 32 vias
v5: diameter 20, hole 8, TOP to BOTTOM, tented both sides, 24 vias
v6: diameter 30, hole 16, TOP to BOTTOM, tented both sides, 17 vias
v7: diameter 20, hole 8, TOP to BOTTOM, tented bottom, 4 vias
v8: diameter 19.68, hole 7.87, TOP to BOTTOM, tented bottom, 4 vias

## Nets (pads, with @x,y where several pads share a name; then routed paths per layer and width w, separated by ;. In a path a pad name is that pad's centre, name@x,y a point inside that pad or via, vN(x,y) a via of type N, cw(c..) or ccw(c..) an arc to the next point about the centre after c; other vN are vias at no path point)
A_RX: C9.2 pad.2@1066.71,1090.22 U10.27 | length 74.5
  TOP w15: C9.2@1061.3,1017.2 1061.3,1056.56 cw(c1074.62,1056.56) 1065.2,1065.98 ccw(c1061.54,1069.64) 1066.71,1069.64 pad.2@1066.71,1090.22
A_TX: C10.2 pad.2@1088.9,1090.22 U10.28 | length 74.5
  TOP w15: pad.2@1088.9,1090.22 U10.28@1088.9,1086.77 1088.9,1069.64 ccw(c1094.07,1069.64) 1090.41,1065.98 cw(c1080.99,1056.56) 1094.31,1056.56 1094.31,1044.53 C10.2@1094.31,1017.2
ANA_IN1: R77.2 R112.2 R117.1 | length 982.7
  TOP w8: R77.2@365.62,1449 v2(365.62,1481.62)
  TOP w10: R117.1@712.62,2125 770.62,2125 R112.2@776,2130.38 788,2118.38 v2(788,2093)
  PWR w6: v2(365.62,1481.62) 365.62,1606.62 458,1699 458,1757.82 573.54,1873.36 573.54,1900.83 646.71,1974 742,1974 788,2020 v2(788,2093)
ANA_IN2: R74.1 R85.2 R120.2 R126.1 | length 1843.4
  TOP w6: R74.1@24.38,1549 24.38,1517.38 v2(29.38,1512.38) ; R85.2@360.73,1249.01 364.01,1249.01 v2(439.21,1324.21)
  TOP w8: R120.2@473,1903.38 473,1894.21 v2(496.75,1870.46) 511.21,1856 600.76,1856 633.97,1889.21 762.21,1889.21 774,1901 774,1950 749,1975 R126.1@712.62,1975
  BOTTOM w6: v2(29.38,1512.38) 29.38,1472.62 101,1401 303,1401 378,1326 437,1326 532.21,1421.21 532.21,1499.21 382.21,1649.21 382.21,1693.5 404.93,1716.21 449.21,1716.21 499.38,1766.38 499.38,1831.23 496.75,1833.85 v2(496.75,1870.46)
ANA_IN3: R88.1 R89.2 R121.2 R127.1 | length 1638.7
  TOP w6: v2(-10.61,1147.12) 21.5,1147.12 R88.1@24.38,1150 74.38,1100 335.38,1100 359.33,1123.96 R89.2@359.33,1149.11 ; R121.2@215.38,1909 181.21,1909 151,1939.21 151,1987 v2(179,2015) R127.1@215.38,2015
  BOTTOM w6: v2(-10.61,1147.12) -26.87,1163.37 -26.87,1551.93 240.8,1819.59 240.8,1953.2 v2(179,2015)
ANA_IN4: R81.2 R113.2 R115.1 | length 1065
  TOP w6: R113.2@143,2163.38 143,2160.43 151.55,2151.88 151.55,2142.45 v2(179,2115) R115.1@215.38,2115 ; R81.2@366.62,1349 391,1349 489,1447 v2(489,1473)
  BOTTOM w6: v2(179,2115) 271.07,2022.93 271.07,1874.04 323.56,1821.55 323.56,1628.26 446.93,1504.89 457.11,1504.89 v2(489,1473)
CC_COEX_BLE: R61.1 R62.1 R101.2 R102.1 U10.50 | length 3516.4
  TOP w6: R101.2@363.62,704 v2(394.21,704) ; v2(1127,1599) 1137,1589 1137,1472 1147.95,1461.05 U10.50@1147.95,1433.23 ; v1@1641.79,1798.41 R62.1@1641.79,1892.69 ; v2(1677.69,1530.28) 1677.69,1519.37 1682.42,1514.63 R61.1@1717,1514.63 ; v2(1685.45,1400) R102.1@1716.38,1400
  PWR w6: v2(394.21,704) 421.74,731.53 544.53,731.53 623.82,810.82 999.89,810.82 1011.68,799.03 1026.37,799.03 1045.38,818.04 1113.37,818.04 1180.33,751.08 1216.04,751.08 1238.7,773.75 1238.7,808.46 1306.86,876.61 1348.52,876.61 1381.48,843.66 1550.15,843.66 1688.4,981.9 1688.4,1030.22 1717.94,1059.76 1717.94,1367.51 v2(1685.45,1400) 1614.6,1470.85 1614.6,1662.2 1641.79,1689.4 v1@1641.79,1798.41 ; 1615.35,1530.28 v2(1677.69,1530.28)
  BOTTOM w6: v2(1127,1599) 1170,1556 1504,1556 1537.21,1522.79 1606.63,1522.79 1664.44,1464.98 1664.44,1421.01 v2(1685.45,1400)
  other v1: 1641.72,1800.96
CC_COEX_SW_OUT: R60.1 R63.1 R123.2 U10.58 | length 2657.7
  TOP w6: R123.2@519.21,1903.38 539.59,1883 v2(549.37,1883) ; v2(796,1605) 837.92,1605 990.47,1452.45 U10.58@990.47,1433.23 ; v1(1403.2,2127.89) 1403.2,2051.38 1497.25,1957.33 1704.14,1957.33 1775.36,1886.1 1775.36,1842.76 R63.1@1793.53,1824.58 v2@1747.09,1824.58 ; v2(1640.47,1627.72) 1652.27,1627.72 1658.05,1621.94 R60.1@1715.23,1621.94
  PWR w6: v2(1640.47,1627.72) 1640.47,1669.69 1654.79,1684.01 1654.79,1732.28 v2(1746.37,1823.86)
  BOTTOM w6: v2(549.37,1883) 666.41,1765.96 666.41,1742.55 762.63,1646.33 762.63,1638.37 v2(796,1605) 805.65,1614.65 805.65,1745.58 923.23,1863.16 923.23,2054.02 997.09,2127.89 v1(1403.2,2127.89)
CC_COEX_WAKEUP: R69.2 R78.1 U10.18 | length 1957.2
  TOP w6: v2(845,1060) 874.91,1060 892.05,1077.14 U10.18@892.05,1086.77 ; v2(1664.21,1584.21) 1773.12,1584.21 1784.85,1595.94 1974.03,1595.94 2007.3,1629.21 v2(2078.62,1629.21) R69.2@2078.62,1598 ; v2(1681,1184) 1715,1150 R78.1@1716.38,1150
  BOTTOM w6: v2(845,1060) 868.47,1083.46 1147.47,1083.46 1189.85,1125.85 1189.85,1137.27 1239.82,1187.23 1312.96,1187.23 1348.36,1151.83 1371.11,1151.83 1403.28,1184 v2(1681,1184) 1740.31,1243.3 1740.31,1508.12 v2(1664.21,1584.21)
CC_NRESET: C49.1 D5.1 J4.10 J8.10 J13.2 Q1.1 R41.2 SW1.4 U10.32 | length 7026
  TOP w6: J13.2@615,1819 614,1820 640.92,1846.92 v2(640.92,1857.82) ; SW1.4@714.7,3823.02 714.7,3812.92 891.28,3636.33 1220.61,3636.33 1269.6,3587.35 Q1.1@1269.6,3543.76 1335.45,3477.91 1421.78,3477.91 1454.3,3445.39 1454.3,3168.84 1450.14,3164.68 v2(1450.14,2615) ; U10.32@1167.64,1086.77 1167.64,1080 1173.95,1073.68 1188.26,1073.68 1225.38,1036.56 1225.38,989.64 1270.77,944.25 R41.2@1290.77,944.25 1292.73,944.25 1303.7,933.28 1303.7,905.39 1307.44,901.65 1332.32,876.77 v2(1332.32,837.21) ; v2(1428.66,2705.92) 1449.08,2705.92 ; D5.1@2068.59,1263 v2(2101.69,1263)
  PWR w6: v2(1332.32,837.21) 1351.68,817.85 1653.25,817.85 1678.1,842.7 1697.49,842.7 1708.38,831.81 1708.38,809.31 1689.19,790.12 1689.19,777.8 1705.51,761.48 1731.17,761.48 1784.66,814.97 1784.66,1057 1830.58,1102.92 1987.3,1102.92 2101.69,1217.31 v2(2101.69,1263) 2068.38,1296.32 1832.9,1296.32 1796.74,1332.48 1796.74,1398.5 1705.06,1490.18 1705.06,1618.36 v2@1682.26,1641.16 ; v2@1679.8,1643.62 v2@1682.26,1641.16 ; v2(1682.84,1641.16) v2@1682.26,1641.16
  BOTTOM w6: v2(640.92,1857.82) 809.84,2026.74 809.84,2138.11 ; J4.10@801,2414 801,2184.07 809.84,2175.23 809.84,2149.89 ; v2(1428.66,2705.92) J8.10@1517.36,2704.86 ; v2(1682.84,1641.16) 1656.78,1641.16 1627.72,1670.22 1581.21,1723.42 1557.96,1750.02 1557.96,1857.85 1436.91,1978.9 1436.91,2422.16 1518.24,2503.48 1518.24,2615 v2(1450.14,2615) 1450.14,2614.41 1404.21,2568.48 1404.21,2366.77 1181.44,2144 815.73,2144 ; 809.84,2138.11 815.73,2144 ; 809.84,2138.11 809.84,2149.89 ; 809.84,2149.89 815.73,2144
